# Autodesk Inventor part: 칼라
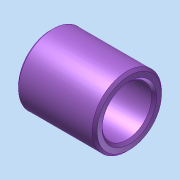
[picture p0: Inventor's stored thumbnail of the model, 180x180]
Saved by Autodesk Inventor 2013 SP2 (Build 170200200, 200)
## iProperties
Created: 2026-01
Part Number: 칼라
Material: Generic
Document SubType Name: Modeling
Designer: a
Density: 1 g/cm^3
Author: a
변환 표준: STEP AP214IS
전처리기: Build: 200, Release: 2013 SP2 Update 6 - Date: Thu 07/17/2014
전송 단위: 밀리미터
불확실성: 0.01
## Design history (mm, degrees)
node "칼라1"
node "솔리드1"
node "기준1"
